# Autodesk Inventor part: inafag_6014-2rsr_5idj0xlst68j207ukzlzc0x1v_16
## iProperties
Shininess: 64.0
Angle Display Precision: 2
Document Length Units: 11269
Document Angle Units: 11279
Document Time Units: 11290
Document Mass Units: 11283
Document Length Units Precision: 3
Document Angle Units Precision: 2
Compacted: True
Created: 2008-08
Part Number: inafag_6014-2rsr_5idj0xlst68j207ukzlzc0x1v_16
Document SubType Name: Modeling
Designer: tpomodeler
Density: 0.0
Volumn: 0.0
Area: 0.0
PropertySet Name: Model Information
Control State: 0
Master: False
Checked Out: False
Author: tpomodeler
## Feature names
1. inafag_6014-2rsr_5idj0xlst68j207ukzlzc0x1v
